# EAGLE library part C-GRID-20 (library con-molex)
CONNECTOR wire to board 2.54 mm (0.100") pitch header
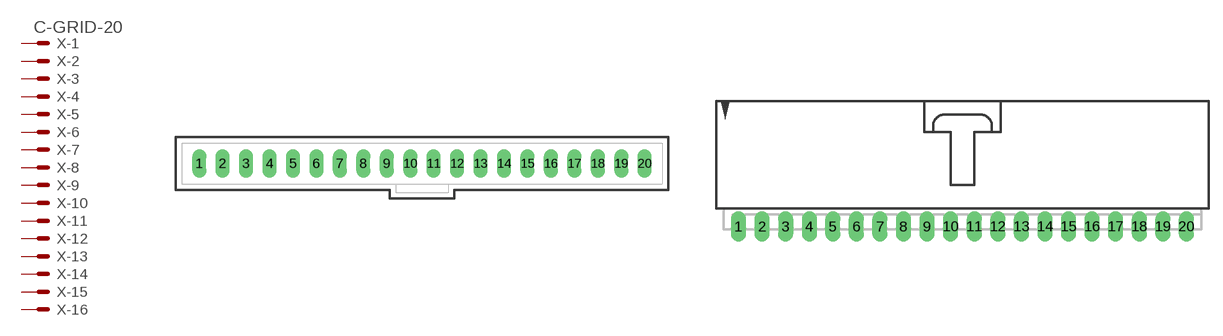
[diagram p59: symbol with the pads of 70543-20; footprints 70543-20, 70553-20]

Designator prefix X; gates -1=MV -2=M -3=M -4=M -5=M -6=M -7=M -8=M -9=M -10=M -11=M -12=M -13=M -14=M -15=M -16=M -17=M -18=M -19=M -20=M

## C-GRID-20-70543 (OC_FARNELL: unknown; OC_NEWARK: unknown)  [70543-20]
1  -1:S  pas
2  -2:S  pas
3  -3:S  pas
4  -4:S  pas
5  -5:S  pas
6  -6:S  pas
7  -7:S  pas
8  -8:S  pas
9  -9:S  pas
10  -10:S  pas
11  -11:S  pas
12  -12:S  pas
13  -13:S  pas
14  -14:S  pas
15  -15:S  pas
16  -16:S  pas
17  -17:S  pas
18  -18:S  pas
19  -19:S  pas
20  -20:S  pas

## C-GRID-20-70553 (OC_FARNELL: unknown; OC_NEWARK: unknown)  [70553-20]
Pads as for 70543-20

## Footprint 70543-20 (pad centres in mm)
C-Grid SL Connector vertical, 20 pin
drill 1.016 long: 1 -24.13,0; 2 -21.59,0; 3 -19.05,0; 4 -16.51,0; 5 -13.97,0; 6 -11.43,0; 7 -8.89,0; 8 -6.35,0; 9 -3.81,0; 10 -1.27,0; 11 1.27,0; 12 3.81,0; 13 6.35,0; 14 8.89,0; 15 11.43,0; 16 13.97,0; 17 16.51,0; 18 19.05,0; 19 21.59,0; 20 24.13,0

## Footprint 70553-20 (pad centres in mm)
C-Grid SL Connector right angle, 20 pin
drill 1.092 long: 1 -24.13,-7.62; 2 -21.59,-7.62; 3 -19.05,-7.62; 4 -16.51,-7.62; 5 -13.97,-7.62; 6 -11.43,-7.62; 7 -8.89,-7.62; 8 -6.35,-7.62; 9 -3.81,-7.62; 10 -1.27,-7.62; 11 1.27,-7.62; 12 3.81,-7.62; 13 6.35,-7.62; 14 8.89,-7.62; 15 11.43,-7.62; 16 13.97,-7.62; 17 16.51,-7.62; 18 19.05,-7.62; 19 21.59,-7.62; 20 24.13,-7.62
